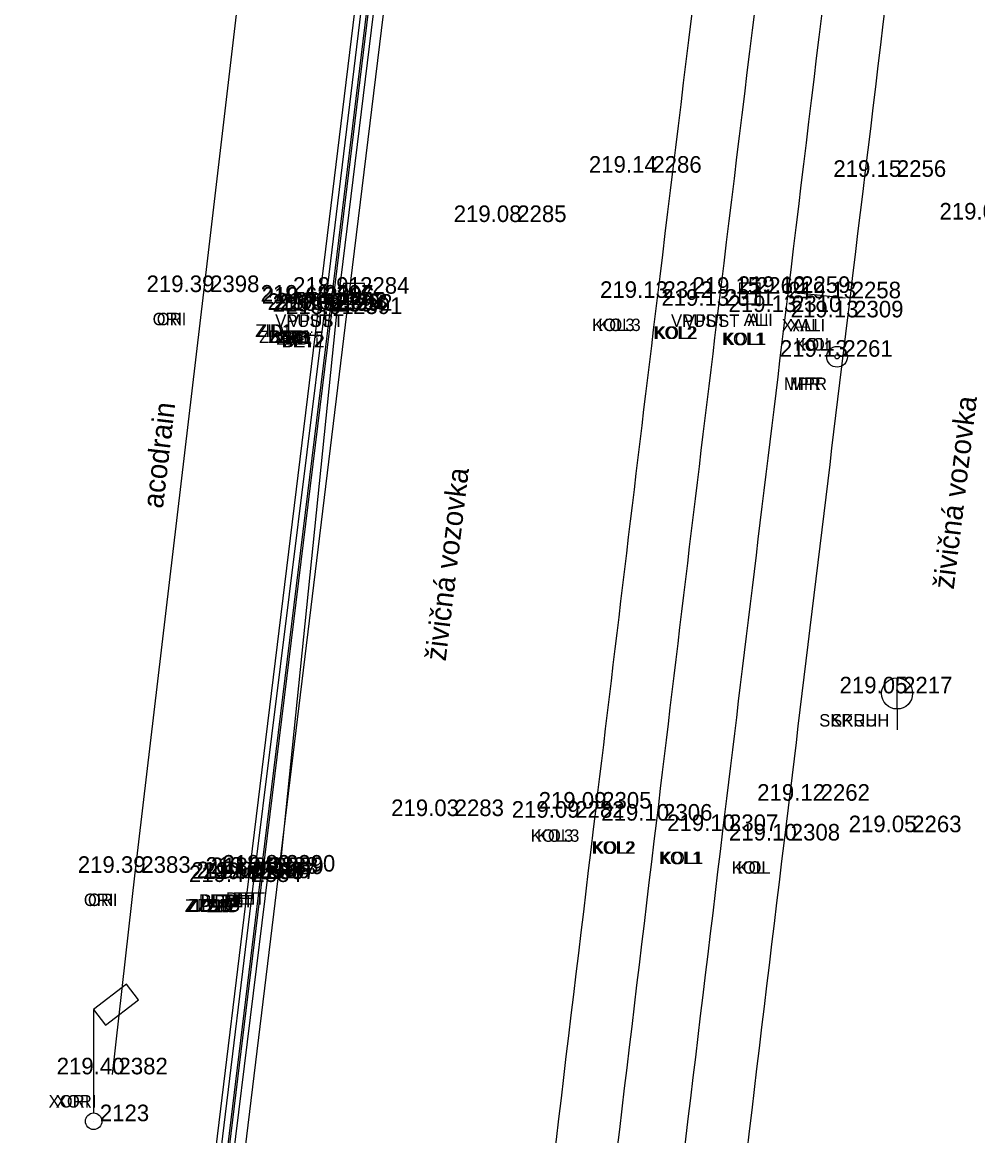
# Model space of a CAD drawing. Extents: x -471047 to -470889, y -1102859 to -1102000.
# Drawn here: x -470955.98 to -470932.93, y -1102264.55 to -1102237.69 of the extents above; entities that cross this region are included whole.
import ezdxf

# ---------------------------------------------------------------- set-up
doc = ezdxf.new("R2010")
doc.units = 0
for name, color, linetype in [('Vrstva 1', 7, 'Continuous'), ('Vrstva 2', 7, 'Continuous'), ('Vrstva 20', 7, 'Continuous'), ('Vrstva 22', 7, 'Continuous'), ('Vrstva 23', 7, 'Continuous'), ('Vrstva 25', 7, 'Continuous'), ('Vrstva 26', 7, 'Continuous'), ('Vrstva 29', 7, 'Continuous'), ('Vrstva 3', 7, 'Continuous'), ('Vrstva 34', 7, 'Continuous'), ('Vrstva 35', 7, 'Continuous'), ('Vrstva 36', 7, 'Continuous'), ('Vrstva 38', 7, 'Continuous'), ('Vrstva 5', 7, 'Continuous'), ('Vrstva 7', 7, 'Continuous'), ('Vrstva 8', 7, 'Continuous')]:
    doc.layers.add(name, color=color, linetype=linetype)

msp = doc.modelspace()

# ---------------------------------------------------------------- linework, layer by layer
at = {"layer": 'Vrstva 1'}
for points in [[(-471040.344, -1102858.385), (-471031.676, -1102846.187), (-471026.357, -1102838.629), (-471023.212, -1102833.975), (-471019.21, -1102827.465), (-471016.861, -1102823.272), (-471013.099, -1102815.912), (-471010.824, -1102810.955), (-471007.329, -1102802.292), (-471005.34, -1102796.515), (-471002.842, -1102787.838), (-471001.3, -1102780.997), (-471000.19, -1102774.713), (-470999.247, -1102768.204), (-470998.794, -1102764.784), (-470997.199, -1102751.812), (-470994.899, -1102732.807), (-470992.551, -1102713.262), (-470990.326, -1102694.887), (-470988.122, -1102676.57), (-470985.812, -1102657.305), (-470983.537, -1102638.407), (-470981.386, -1102620.622), (-470979.843, -1102608.014), (-470976.377, -1102579.253), (-470972.945, -1102550.69), (-470970.475, -1102530.206), (-470967.905, -1102508.801), (-470965.053, -1102485.131), (-470962.734, -1102465.9), (-470960.173, -1102444.812), (-470957.795, -1102425.103), (-470954.965, -1102401.839), (-470953.834, -1102392.574), (-470952.33, -1102379.985), (-470950.744, -1102366.853), (-470948.978, -1102352.106), (-470947.037, -1102335.844), (-470944.949, -1102318.462), (-470944.013, -1102310.745), (-470942.39, -1102297.267), (-470939.519, -1102273.45), (-470937.593, -1102257.43), (-470936.064, -1102244.81), (-470934.114, -1102228.634), (-470931.621, -1102207.856), (-470929.536, -1102190.857), (-470926.572, -1102166.31), (-470924.91, -1102152.663), (-470923.413, -1102140.333), (-470921.923, -1102127.669), (-470921.155, -1102120.084), (-470920.446, -1102109.574), (-470919.912, -1102099.137), (-470919.63, -1102088.981), (-470919.523, -1102081.193), (-470919.563, -1102070.395), (-470919.714, -1102064.236), (-470920.134, -1102054.704), (-470920.462, -1102047.615), (-470920.599, -1102044.52), (-470920.743, -1102041.873), (-470921.125, -1102034.455), (-470921.774, -1102030.337), (-470922.418, -1102027.787), (-470923.734, -1102023.93), (-470924.872, -1102021.434), (-470926.752, -1102018.182), (-470927.953, -1102016.45), (-470929.616, -1102014.424), (-470932.252, -1102011.756), (-470935.111, -1102009.425), (-470938.391, -1102007.371), (-470942.651, -1102005.401)], [(-471041.328, -1102857.18), (-471032.144, -1102844.242), (-471027.583, -1102837.763), (-471024.388, -1102833.028), (-471020.451, -1102826.6), (-471018.089, -1102822.378), (-471014.542, -1102815.445), (-471012.233, -1102810.418), (-471009.247, -1102803.108), (-471006.795, -1102796.098), (-471004.315, -1102787.532), (-471002.782, -1102780.723), (-471001.674, -1102774.458), (-471000.75, -1102768.095), (-471000.28, -1102764.601), (-470998.692, -1102751.741), (-470996.378, -1102732.635), (-470994.028, -1102713.058), (-470991.808, -1102694.749), (-470989.616, -1102676.447), (-470987.284, -1102657.013), (-470985.031, -1102638.272), (-470982.87, -1102620.431), (-470981.334, -1102607.933), (-470977.881, -1102579.263), (-470974.429, -1102550.492), (-470971.964, -1102530.054), (-470969.391, -1102508.607), (-470966.54, -1102484.984), (-470964.231, -1102465.853), (-470961.679, -1102444.752), (-470959.304, -1102425.078), (-470956.455, -1102401.634), (-470955.339, -1102392.489), (-470953.812, -1102379.71), (-470952.249, -1102366.808), (-470950.479, -1102352.023), (-470948.536, -1102335.868), (-470946.426, -1102318.233), (-470945.493, -1102310.531), (-470943.864, -1102297.013), (-470940.984, -1102273.071), (-470939.078, -1102257.195), (-470937.559, -1102244.684), (-470935.592, -1102228.353), (-470933.101, -1102207.653), (-470931.011, -1102190.57), (-470928.046, -1102166.021), (-470926.409, -1102152.578), (-470924.898, -1102140.121), (-470923.427, -1102127.544), (-470922.647, -1102119.826), (-470921.919, -1102109.229), (-470921.42, -1102099.134), (-470921.127, -1102089.016), (-470921.023, -1102081.453), (-470921.061, -1102070.468), (-470921.209, -1102064.314), (-470921.666, -1102053.966), (-470922.156, -1102043.345), (-470922.299, -1102039.934), (-470922.637, -1102034.36), (-470923.091, -1102031.241), (-470923.847, -1102028.247), (-470925.083, -1102024.594), (-470926.222, -1102022.086), (-470928.04, -1102018.943), (-470929.138, -1102017.357), (-470930.929, -1102015.175), (-470933.062, -1102013.049), (-470936.379, -1102010.368), (-470939.169, -1102008.662), (-470942.899, -1102006.906), (-470945.661, -1102005.908)], [(-471043.557, -1102855.955), (-471035.129, -1102844.026), (-471029.872, -1102836.499), (-471026.577, -1102831.578), (-471022.675, -1102825.415), (-471020.123, -1102821.053), (-471016.667, -1102814.59), (-471014.208, -1102809.45), (-471011.177, -1102802.451), (-471008.55, -1102795.333), (-471006.082, -1102787.209), (-471004.464, -1102780.376), (-471003.265, -1102774.167), (-471002.327, -1102767.948), (-471001.636, -1102762.527), (-471000.297, -1102751.605), (-470997.959, -1102732.524), (-470995.602, -1102712.802), (-470993.412, -1102694.623), (-470991.21, -1102676.17), (-470988.891, -1102656.857), (-470986.625, -1102638.083), (-470984.455, -1102620.195), (-470982.936, -1102607.733), (-470979.497, -1102579.223), (-470976.023, -1102550.279), (-470973.554, -1102529.822), (-470970.991, -1102508.497), (-470968.146, -1102484.787), (-470965.835, -1102465.72), (-470963.284, -1102444.529), (-470960.91, -1102424.942), (-470958.043, -1102401.343), (-470956.946, -1102392.356), (-470955.396, -1102379.408), (-470953.851, -1102366.636), (-470952.049, -1102351.733), (-470950.124, -1102335.611), (-470948.034, -1102318.083), (-470947.094, -1102310.328), (-470945.421, -1102296.51), (-470942.58, -1102272.848), (-470940.675, -1102256.948), (-470939.176, -1102244.526), (-470937.187, -1102228.174), (-470934.708, -1102207.467), (-470932.621, -1102190.433), (-470929.634, -1102165.778), (-470928.004, -1102152.415), (-470926.45, -1102139.595), (-470925.003, -1102127.418), (-470924.249, -1102119.695), (-470923.515, -1102109.093), (-470923.018, -1102099.069), (-470922.711, -1102088.911), (-470922.643, -1102081.356), (-470922.797, -1102070.414), (-470923.018, -1102064.454), (-470923.52, -1102053.203), (-470923.823, -1102047.529), (-470924.123, -1102041.506), (-470924.462, -1102037.486), (-470924.934, -1102031.904), (-470925.664, -1102028.672), (-470926.771, -1102025.506), (-470927.959, -1102022.914), (-470929.674, -1102020.028), (-470930.76, -1102018.498), (-470932.447, -1102016.478), (-470935.215, -1102013.816), (-470937.644, -1102011.98), (-470940.381, -1102010.371), (-470943.968, -1102008.669), (-470947.145, -1102007.524), (-470950.874, -1102006.74)], [(-471044.756, -1102855.056), (-471036.376, -1102843.177), (-471031.167, -1102835.741), (-471027.859, -1102830.8), (-471023.934, -1102824.593), (-471021.43, -1102820.312), (-471018.011, -1102813.91), (-471015.536, -1102808.75), (-471012.578, -1102801.897), (-471009.95, -1102794.77), (-471007.561, -1102786.914), (-471005.936, -1102780.074), (-471004.727, -1102773.818), (-471003.828, -1102767.827), (-471003.121, -1102762.345), (-471001.787, -1102751.467), (-470999.446, -1102732.348), (-470997.073, -1102712.539), (-470994.902, -1102694.521), (-470992.696, -1102676.023), (-470990.376, -1102656.68), (-470988.131, -1102638.071), (-470985.947, -1102620.018), (-470984.417, -1102607.512), (-470980.993, -1102579.08), (-470977.514, -1102550.137), (-470975.048, -1102529.649), (-470972.488, -1102508.37), (-470969.618, -1102484.508), (-470967.34, -1102465.669), (-470964.767, -1102444.39), (-470962.402, -1102424.781), (-470959.534, -1102401.193), (-470958.432, -1102392.151), (-470956.883, -1102379.208), (-470955.335, -1102366.424), (-470953.535, -1102351.506), (-470951.606, -1102335.399), (-470949.519, -1102317.94), (-470948.575, -1102310.159), (-470946.889, -1102296.144), (-470944.056, -1102272.618), (-470942.139, -1102256.659), (-470940.657, -1102244.341), (-470938.638, -1102227.749), (-470936.19, -1102207.298), (-470934.102, -1102190.255), (-470931.124, -1102165.639), (-470929.492, -1102152.254), (-470927.915, -1102139.252), (-470926.46, -1102127.103), (-470925.74, -1102119.604), (-470925.012, -1102108.913), (-470924.523, -1102099.054), (-470924.217, -1102088.866), (-470924.148, -1102081.334), (-470924.301, -1102070.391), (-470924.518, -1102064.43), (-470924.97, -1102054.435), (-470925.588, -1102041.569), (-470925.963, -1102035.313), (-470926.405, -1102032.225), (-470927.078, -1102029.198), (-470928.123, -1102026.148), (-470929.318, -1102023.558), (-470930.84, -1102020.97), (-470931.868, -1102019.515), (-470933.443, -1102017.605), (-470936.26, -1102014.885), (-470938.429, -1102013.255), (-470941.213, -1102011.639), (-470944.847, -1102009.927), (-470947.723, -1102008.912), (-470951.444, -1102008.161), (-470954.511, -1102007.931), (-470957.895, -1102008.041)]]:
    msp.add_spline(points, degree=3, dxfattribs=at)
at = {"layer": 'Vrstva 2'}
for p, q in [((-470948.683, -1102244.633), (-470946.874, -1102229.715)), ((-470950.392, -1102258.336), (-470948.683, -1102244.633)), ((-470952.07, -1102272.161), (-470950.392, -1102258.336))]:
    msp.add_line(p, q, dxfattribs=at)
at = {"layer": 'Vrstva 20'}
for p, q in [((-470951.6, -1102244.2), (-470949.9, -1102229.729)), ((-470953.258, -1102258.21), (-470951.6, -1102244.2)), ((-470953.807, -1102263.07), (-470953.258, -1102258.21))]:
    msp.add_line(p, q, dxfattribs=at)
at = {"layer": 'Vrstva 23'}
for p, q in [((-470953.466, -1102260.897), (-470954.261, -1102261.502)), ((-470953.176, -1102261.274), (-470953.466, -1102260.897)), ((-470953.974, -1102261.88), (-470953.176, -1102261.274)), ((-470954.261, -1102261.502), (-470954.261, -1102264.002)), ((-470954.261, -1102261.502), (-470953.974, -1102261.88))]:
    msp.add_line(p, q, dxfattribs=at)
msp.add_circle((-470954.261, -1102264.202), 0.2, dxfattribs=at)
at = {"layer": 'Vrstva 25'}
for p, q in [((-470948.23, -1102243.989), (-470948.23, -1102244.489)), ((-470947.73, -1102243.989), (-470948.23, -1102243.989)), ((-470947.73, -1102244.489), (-470947.73, -1102243.989)), ((-470938.679, -1102243.987), (-470938.679, -1102244.487)), ((-470938.179, -1102243.987), (-470938.679, -1102243.987)), ((-470938.179, -1102244.487), (-470938.179, -1102243.987)), ((-470948.23, -1102244.239), (-470947.73, -1102244.239)), ((-470938.679, -1102244.237), (-470938.179, -1102244.237)), ((-470948.23, -1102244.489), (-470947.73, -1102244.489)), ((-470938.679, -1102244.487), (-470938.179, -1102244.487)), ((-470934.876, -1102254.257), (-470934.876, -1102253.507)), ((-470934.876, -1102254.257), (-470934.876, -1102254.757))]:
    msp.add_line(p, q, dxfattribs=at)
msp.add_circle((-470934.876, -1102253.882), 0.375, dxfattribs=at)
at = {"layer": 'Vrstva 26'}
for radius in [0.25, 0.05]:
    msp.add_circle((-470936.323, -1102245.761), radius, dxfattribs=at)
at = {"layer": 'Vrstva 29'}
msp.add_line((-470936.122, -1102244.345), (-470937.335, -1102244.217), dxfattribs=at)
at = {"layer": 'Vrstva 3'}
for p, q in [((-470948.817, -1102244.484), (-470947.026, -1102229.725)), ((-470948.557, -1102244.669), (-470946.729, -1102229.713)), ((-470950.52, -1102258.353), (-470948.817, -1102244.484)), ((-470950.237, -1102258.362), (-470948.557, -1102244.669)), ((-470952.2, -1102272.163), (-470950.52, -1102258.353)), ((-470951.927, -1102272.181), (-470950.237, -1102258.362))]:
    msp.add_line(p, q, dxfattribs=at)
at = {"layer": 'Vrstva 34'}
for p, q in [((-470940.93, -1102241.32), (-470940.93, -1102241.32)), ((-470935.03, -1102241.42), (-470935.03, -1102241.42)), ((-470944.19, -1102242.51), (-470944.19, -1102242.51)), ((-470951.6, -1102244.2), (-470951.6, -1102244.2)), ((-470947.98, -1102244.24), (-470947.98, -1102244.24)), ((-470938.43, -1102244.24), (-470938.43, -1102244.24)), ((-470937.34, -1102244.22), (-470937.34, -1102244.22)), ((-470948.85, -1102244.43), (-470948.85, -1102244.43)), ((-470948.82, -1102244.48), (-470948.82, -1102244.48)), ((-470940.66, -1102244.34), (-470940.66, -1102244.34)), ((-470939.18, -1102244.53), (-470939.18, -1102244.53)), ((-470936.12, -1102244.35), (-470936.12, -1102244.35)), ((-470948.68, -1102244.63), (-470948.68, -1102244.63)), ((-470948.56, -1102244.67), (-470948.56, -1102244.67)), ((-470948.51, -1102244.62), (-470948.51, -1102244.62)), ((-470948.39, -1102244.65), (-470948.39, -1102244.65)), ((-470948.15, -1102244.73), (-470948.15, -1102244.73)), ((-470937.56, -1102244.68), (-470937.56, -1102244.68)), ((-470936.06, -1102244.81), (-470936.06, -1102244.81)), ((-470936.32, -1102245.76), (-470936.32, -1102245.76)), ((-470934.88, -1102253.88), (-470934.88, -1102253.88)), ((-470936.87, -1102256.47), (-470936.87, -1102256.47)), ((-470945.7, -1102256.84), (-470945.7, -1102256.84)), ((-470942.79, -1102256.88), (-470942.79, -1102256.88)), ((-470942.14, -1102256.66), (-470942.14, -1102256.66)), ((-470940.67, -1102256.95), (-470940.67, -1102256.95)), ((-470939.08, -1102257.2), (-470939.08, -1102257.2)), ((-470937.59, -1102257.43), (-470937.59, -1102257.43)), ((-470934.66, -1102257.23), (-470934.66, -1102257.23)), ((-470953.26, -1102258.21), (-470953.26, -1102258.21)), ((-470950.18, -1102258.23), (-470950.18, -1102258.23)), ((-470950.05, -1102258.24), (-470950.05, -1102258.24)), ((-470949.77, -1102258.18), (-470949.77, -1102258.18)), ((-470950.58, -1102258.43), (-470950.58, -1102258.43)), ((-470950.52, -1102258.35), (-470950.52, -1102258.35)), ((-470950.39, -1102258.34), (-470950.39, -1102258.34)), ((-470950.24, -1102258.36), (-470950.24, -1102258.36)), ((-470953.81, -1102263.07), (-470953.81, -1102263.07)), ((-470954.26, -1102264.2), (-470954.26, -1102264.2))]:
    msp.add_line(p, q, dxfattribs=at)
at = {"layer": 'Vrstva 5'}
for p, q in [((-470948.153, -1102244.725), (-470946.323, -1102229.78)), ((-470951.545, -1102272.632), (-470948.153, -1102244.725))]:
    msp.add_line(p, q, dxfattribs=at)
at = {"layer": 'Vrstva 7'}
for p, q in [((-470948.509, -1102244.617), (-470946.706, -1102229.793)), ((-470950.177, -1102258.23), (-470948.509, -1102244.617)), ((-470951.898, -1102272.26), (-470950.177, -1102258.23))]:
    msp.add_line(p, q, dxfattribs=at)
at = {"layer": 'Vrstva 8'}
for p, q in [((-470948.387, -1102244.646), (-470946.564, -1102229.727)), ((-470949.771, -1102258.182), (-470948.387, -1102244.646)), ((-470951.769, -1102272.256), (-470950.053, -1102258.243)), ((-470950.053, -1102258.243), (-470949.771, -1102258.182))]:
    msp.add_line(p, q, dxfattribs=at)

# ---------------------------------------------------------------- texts
at = {"layer": 'Vrstva 22'}
for s, rotation, p in [('acodrain', 83.2508, (-470952.592, -1102249.435)), ('živičná vozovka', 83.0936, (-470933.51, -1102251.386)), ('živičná vozovka', 83.0936, (-470945.769, -1102253.117))]:
    msp.add_text(s, height=0.5, rotation=rotation, dxfattribs=at).set_placement(p)
at = {"layer": 'Vrstva 35'}
for s, p in [('ORI', (-470952.838, -1102245)), ('ORI', (-470952.739, -1102245)), ('VPUST', (-470949.88, -1102245.04)), ('VPUST', (-470949.569, -1102245.04)), ('VPUST', (-470940.33, -1102245.04)), ('VPUST', (-470940.019, -1102245.04)), ('ALI', (-470938.578, -1102245.02)), ('ALI', (-470938.479, -1102245.02)), ('ZID1', (-470950.362, -1102245.28)), ('ZID1', (-470950.32, -1102245.28)), ('KOL3', (-470942.235, -1102245.14)), ('KOL3', (-470942.088, -1102245.14)), ('KOL2', (-470940.755, -1102245.33)), ('KOL2', (-470940.721, -1102245.33)), ('XALI', (-470937.658, -1102245.15)), ('XALI', (-470937.484, -1102245.15)), ('ZZAB', (-470950.269, -1102245.43)), ('ZZAB', (-470950.044, -1102245.43)), ('BET1', (-470950.052, -1102245.42)), ('BET1', (-470950.01, -1102245.42)), ('ZID', (-470949.851, -1102245.47)), ('BET2', (-470949.725, -1102245.53)), ('ZID', (-470949.699, -1102245.47)), ('BET2', (-470949.691, -1102245.53)), ('BET', (-470949.69, -1102245.45)), ('BET', (-470949.529, -1102245.45)), ('KOL1', (-470939.102, -1102245.48)), ('KOL1', (-470939.06, -1102245.48)), ('KOL', (-470937.335, -1102245.61)), ('KOL', (-470937.199, -1102245.61)), ('MPR', (-470937.609, -1102246.56)), ('MPR', (-470937.459, -1102246.56)), ('SKRUH', (-470936.755, -1102254.68)), ('SKRUH', (-470936.469, -1102254.68)), ('KOL3', (-470943.715, -1102257.46)), ('KOL3', (-470943.568, -1102257.46)), ('KOL2', (-470942.245, -1102257.75)), ('KOL2', (-470942.211, -1102257.75)), ('KOL1', (-470940.622, -1102258)), ('KOL1', (-470940.58, -1102258)), ('KOL', (-470938.865, -1102258.23)), ('KOL', (-470938.729, -1102258.23)), ('ORI', (-470954.498, -1102259.01)), ('ORI', (-470954.399, -1102259.01)), ('BET1', (-470951.722, -1102259.03)), ('BET1', (-470951.68, -1102259.03)), ('BET', (-470951.35, -1102259.04)), ('BET', (-470951.189, -1102259.04)), ('BET', (-470951.07, -1102258.98)), ('BET', (-470950.909, -1102258.98)), ('ZID1', (-470952.062, -1102259.15)), ('ZID1', (-470952.02, -1102259.15)), ('ZZAB', (-470951.979, -1102259.14)), ('ZZAB', (-470951.754, -1102259.14)), ('ZID', (-470951.531, -1102259.16)), ('ZID', (-470951.379, -1102259.16)), ('XORI', (-470955.348, -1102263.87)), ('XORI', (-470955.174, -1102263.87))]:
    msp.add_text(s, height=0.3, dxfattribs=at).set_placement(p)
at = {"layer": 'Vrstva 36'}
for s, p in [(' 2286', (-470940.93, -1102241.32)), (' 2256', (-470935.03, -1102241.42)), (' 2285', (-470944.19, -1102242.51)), (' 2398', (-470951.6, -1102244.2)), (' 2397', (-470948.85, -1102244.43)), (' 2284', (-470947.98, -1102244.24)), (' 2312', (-470940.66, -1102244.34)), (' 2260', (-470938.43, -1102244.24)), (' 2259', (-470937.34, -1102244.22)), (' 2258', (-470936.12, -1102244.35)), (' 2396', (-470948.82, -1102244.48)), (' 2395', (-470948.68, -1102244.63)), (' 2394', (-470948.56, -1102244.67)), (' 2393', (-470948.51, -1102244.62)), (' 2392', (-470948.39, -1102244.65)), (' 2311', (-470939.18, -1102244.53)), (' 2310', (-470937.56, -1102244.68)), (' 2391', (-470948.15, -1102244.73)), (' 2309', (-470936.06, -1102244.81)), (' 2261', (-470936.32, -1102245.76)), (' 2217', (-470934.88, -1102253.88)), (' 2262', (-470936.87, -1102256.47)), (' 2305', (-470942.14, -1102256.66)), (' 2283', (-470945.7, -1102256.84)), (' 2282', (-470942.79, -1102256.88)), (' 2306', (-470940.67, -1102256.95)), (' 2307', (-470939.08, -1102257.2)), (' 2263', (-470934.66, -1102257.23)), (' 2308', (-470937.59, -1102257.43)), (' 2383', (-470953.26, -1102258.21)), (' 2385', (-470950.52, -1102258.35)), (' 2386', (-470950.39, -1102258.34)), (' 2387', (-470950.24, -1102258.36)), (' 2388', (-470950.18, -1102258.23)), (' 2389', (-470950.05, -1102258.24)), (' 2390', (-470949.77, -1102258.18)), (' 2384', (-470950.58, -1102258.43)), (' 2382', (-470953.81, -1102263.07)), (' 2123', (-470954.26, -1102264.2))]:
    msp.add_text(s, height=0.4, dxfattribs=at).set_placement(p)
at = {"layer": 'Vrstva 38'}
for s, p in [('219.14 ', (-470942.312, -1102241.32)), ('219.15 ', (-470936.414, -1102241.42)), ('219.08 ', (-470945.574, -1102242.51)), ('219.07 ', (-470933.853, -1102242.45)), ('219.39 ', (-470952.984, -1102244.2)), ('219.44 ', (-470950.232, -1102244.43)), ('218.91 ', (-470949.45, -1102244.24)), ('219.13 ', (-470942.043, -1102244.34)), ('219.15 ', (-470939.814, -1102244.24)), ('219.12 ', (-470938.721, -1102244.22)), ('219.13 ', (-470937.503, -1102244.35)), ('219.63 ', (-470950.203, -1102244.48)), ('219.63 ', (-470950.063, -1102244.63)), ('219.63 ', (-470949.943, -1102244.67)), ('219.06 ', (-470949.87, -1102244.62)), ('218.92 ', (-470949.771, -1102244.65)), ('219.13 ', (-470940.563, -1102244.53)), ('219.13 ', (-470938.943, -1102244.68)), ('218.91 ', (-470949.62, -1102244.73)), ('219.13 ', (-470937.443, -1102244.81)), ('219.13 ', (-470937.703, -1102245.76)), ('219.05 ', (-470936.264, -1102253.88)), ('219.12 ', (-470938.251, -1102256.47)), ('219.09 ', (-470943.524, -1102256.66)), ('219.03 ', (-470947.083, -1102256.84)), ('219.09 ', (-470944.174, -1102256.88)), ('219.10 ', (-470942.013, -1102256.95)), ('219.10 ', (-470940.423, -1102257.2)), ('219.05 ', (-470936.044, -1102257.23)), ('219.10 ', (-470938.933, -1102257.43)), ('219.39 ', (-470954.644, -1102258.21)), ('219.65 ', (-470951.904, -1102258.35)), ('219.65 ', (-470951.774, -1102258.34)), ('219.65 ', (-470951.624, -1102258.36)), ('219.04 ', (-470951.562, -1102258.23)), ('218.89 ', (-470951.434, -1102258.24)), ('218.89 ', (-470951.154, -1102258.18)), ('219.44 ', (-470951.962, -1102258.43)), ('219.40 ', (-470955.153, -1102263.07))]:
    msp.add_text(s, height=0.4, dxfattribs=at).set_placement(p)

doc.saveas('drawing.dxf')
